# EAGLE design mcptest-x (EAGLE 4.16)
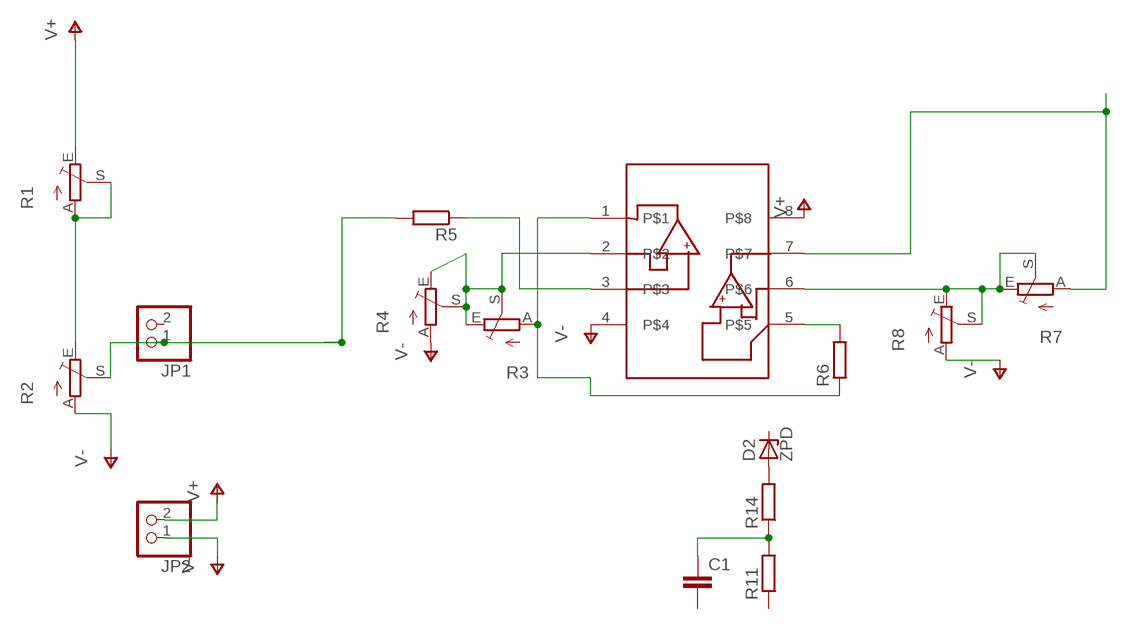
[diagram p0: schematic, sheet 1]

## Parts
C1  C-EU025_050-035X075  [C025_050-035X075]
D2  ZPD  [DO35Z10]
JP1  PINHD-1X2  [1X02]
JP2  PINHD-1X2  [1X02]
R1  TRIM_EU-LI15  [LI15]
R2  TRIM_EU-LI15  [LI15]
R3  TRIM_EU-LI15  [LI15]
R4  TRIM_EU-LI15  [LI15]
R5  R-EU_0207/15  [0207/15]
R6  R-EU_0207/15  [0207/15]
R7  TRIM_EU-LI15  [LI15]
R8  TRIM_EU-LI15  [LI15]
R11  R-EU_0207/10  [0207/10]
R14  R-EU_0207/10  [0207/10]
U$1  MCP6042SOIC  [SO-08]

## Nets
N$1: R7.A U$1.7
N$2: R7.E R7.S R8.E R8.S U$1.6
N$3: R3.E R3.S R4.E R4.S U$1.2
N$4: R3.A R6.1 U$1.1
N$5: R6.2 U$1.5
N$6: R1.A R1.S R2.E
N$7: R5.1 U$1.3
N$8: JP1.1 R2.S R5.2
N$9: C1.1 R11.2 R14.1
N$11: D2.A R14.2
V+: JP2.2 R1.E U$1.8
V-: JP2.1 R2.A R4.A R8.A U$1.4
Unconnected: C1.2 D2.C JP1.2 R11.1

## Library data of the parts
C1 = rcl:C-EU: CAPACITOR, European symbol
D2 = diode:ZPD: Z DIODE
JP1 JP2 = pinhead:PINHD-1X2: PIN HEADER
R1-R4 R7 R8 = pot:TRIM_EU-: POTENTIOMETER
R5 R6 = rcl:R-EU_: RESISTOR, European symbol
R11 R14 = rcl-2:R-EU_: RESISTOR, European symbol
U$1 = microchip-3:MCP6042

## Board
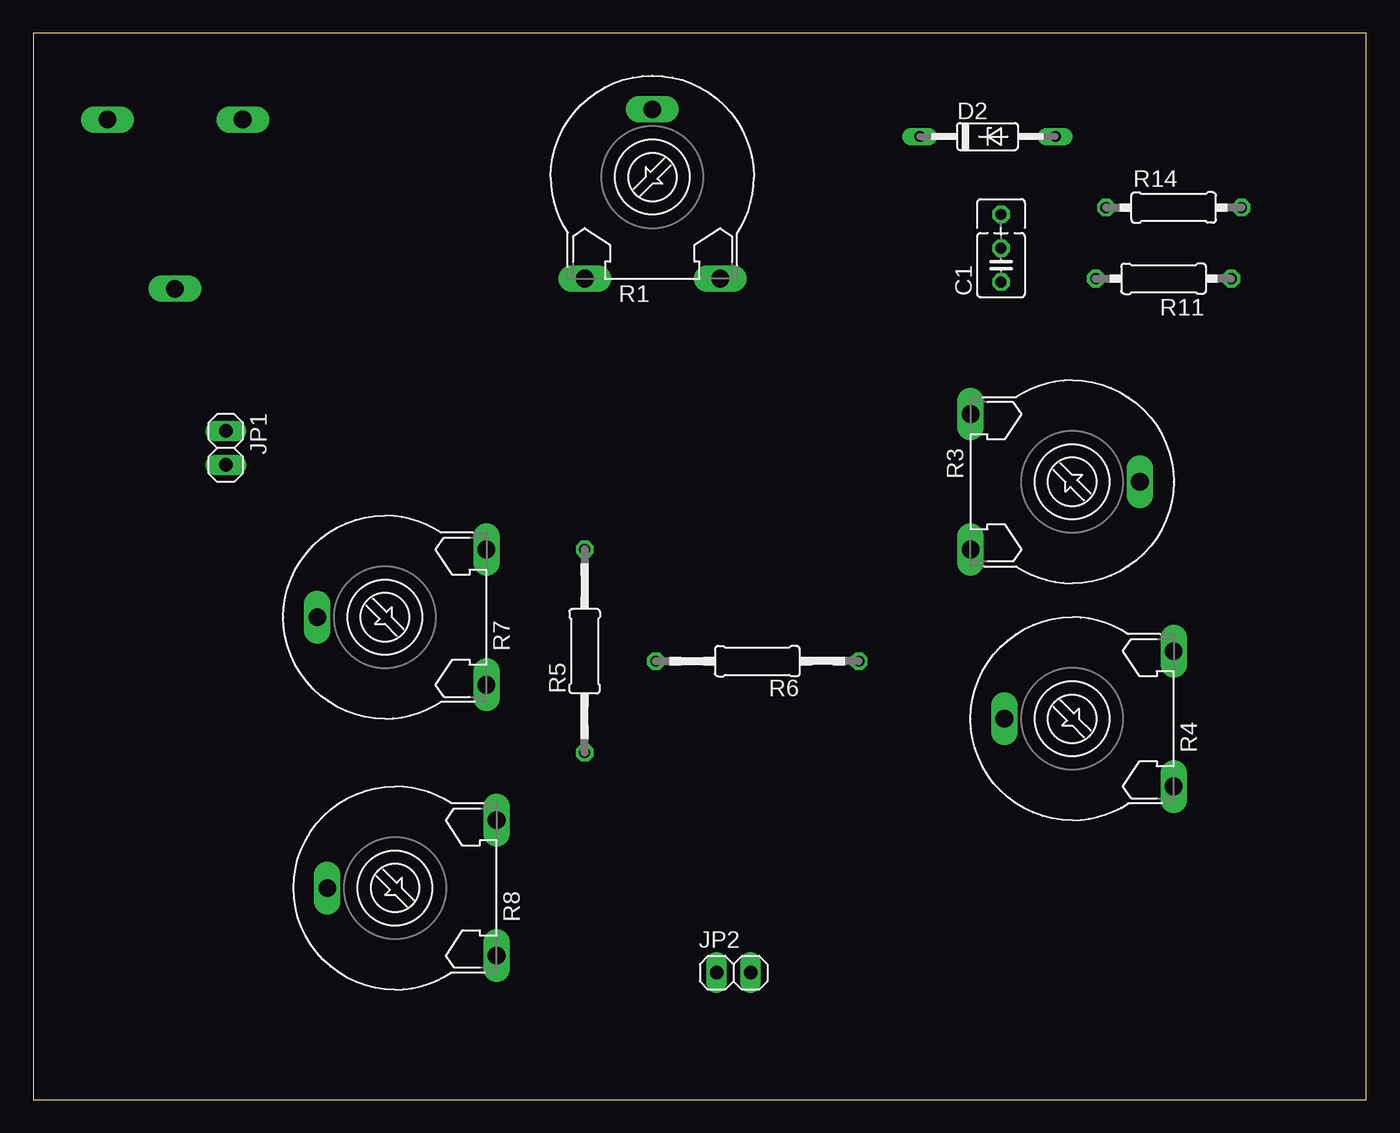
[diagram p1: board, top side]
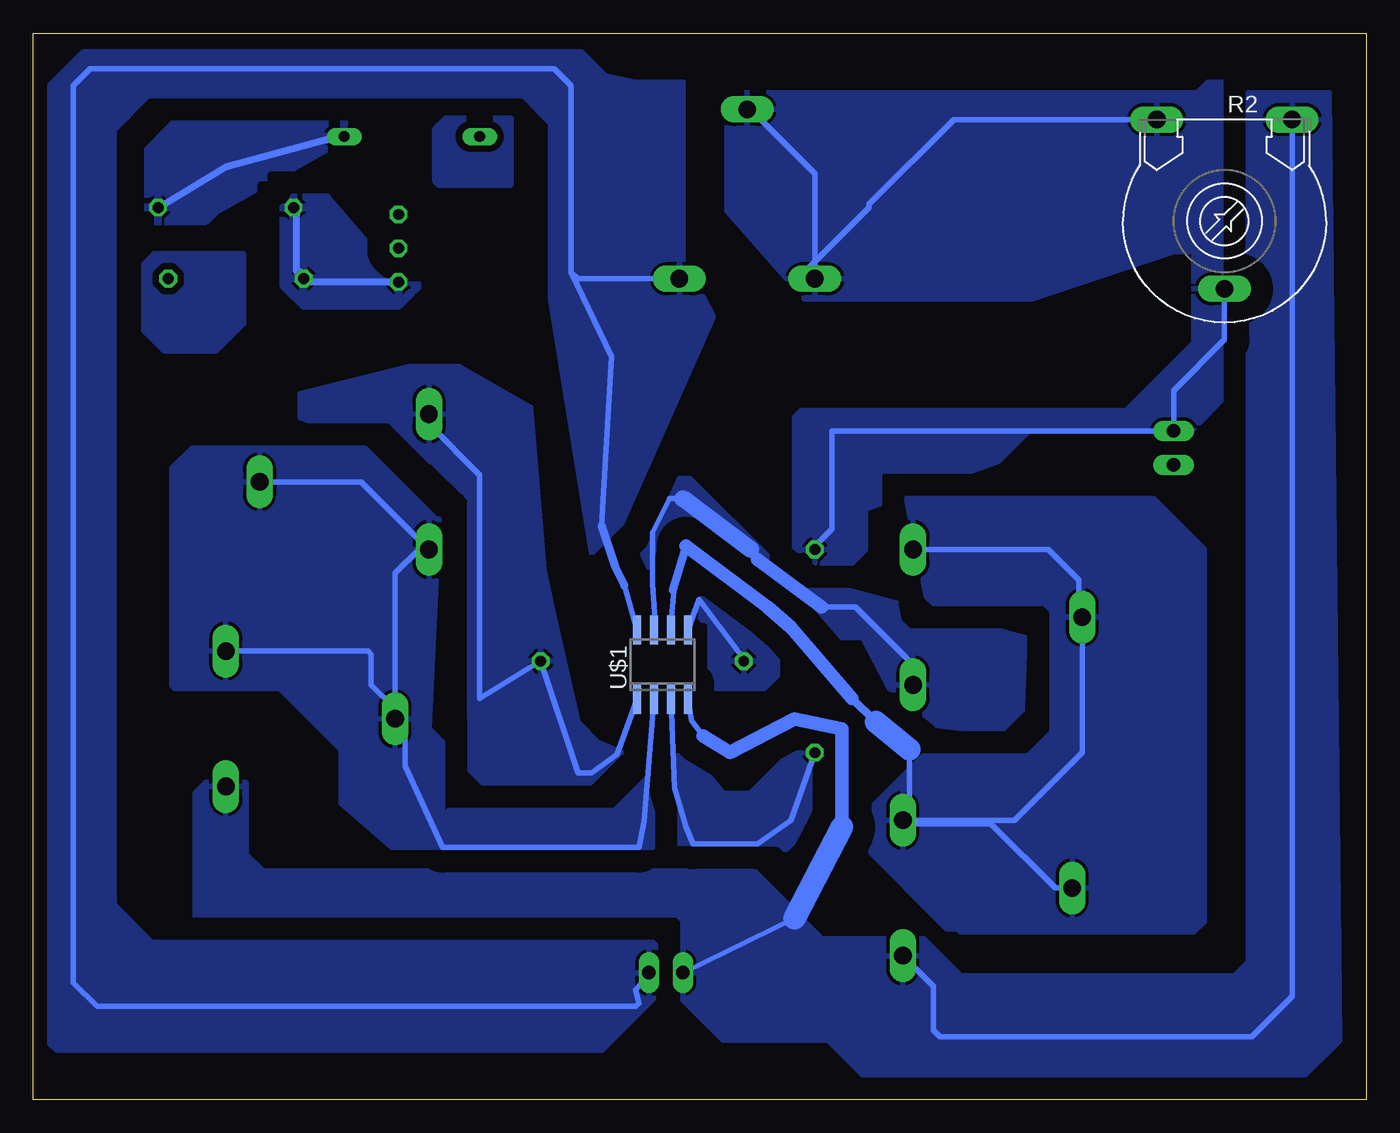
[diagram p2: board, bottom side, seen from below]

Size 100 x 80 mm. Coordinates in mm from the lower left corner, seen from the top.
Outline: 0,0 100,0 100,80 0,80 0,0
Copper layers (1*16): Top 0.035mm / dielectric 1.5mm / Bottom 0.035mm
Design rules "default": minimum track width 20mil, minimum drill 24mil, track to track 20mil, track to pad 20mil, pad to pad 8mil, via to via 8mil, smd to smd 8mil, copper to edge 40mil, drill to drill 8mil, minimum pad ring 10mil, minimum via ring 8mil, stop-mask expansion 4mil, vias tented up to drill 0mil, thermal gap 10mil

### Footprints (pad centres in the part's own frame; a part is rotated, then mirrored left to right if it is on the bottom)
C025_050-035X075 = drill 0.813 octagon: 1 -1.27,0; 2 1.27,0; 3 3.81,0
DO35Z10 = drill 0.813 long: A 5.08,0; C -5.08,0
1X02 = drill 1.016 long: 1 -1.27,0; 2 1.27,0
LI15 = drill 1.321 long: A -5.08,-7.62; E 5.08,-7.62; S 0,5.08
0207/15 = drill 0.813 octagon: 1 -7.62,0; 2 7.62,0
0207/10 = drill 0.813 octagon: 1 -5.08,0; 2 5.08,0
SO-08 = smd 0.6 x 2.2: 1 -1.905,-2.6; 2 -0.635,-2.6; 3 0.635,-2.6; 4 1.905,-2.6; 5 1.905,2.6; 6 0.635,2.6; 7 -0.635,2.6; 8 -1.905,2.6

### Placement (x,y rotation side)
C1  72.61,62.61 90 top
D2  71.59,72.26 0 top
JP1  14.44,48.89 270 top
JP2  52.54,9.52 0 top
R1  46.44,69.21 0 top
R2  10.63,65.91 180 bottom
R3  77.94,46.35 270 top
R4  77.94,28.57 90 top
R5  41.36,33.65 90 top
R6  54.32,32.89 180 top
R7  26.38,36.19 90 top
R8  27.14,15.87 90 top
R11  84.8,61.59 180 top
R14  85.56,66.92 0 top
U$1  52.79,32.63 0 bottom

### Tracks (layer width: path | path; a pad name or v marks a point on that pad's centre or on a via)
N$1
  Bottom 0.406: R7.A 34,32.63 38.32,36.95 40.86,36.95 | 45.68,40.51 46.19,41.27 | 51.27,45.08 52.29,45.08 53.56,42.54 53.56,38.73 53.3,35.43 53.43,35.3 U$1.7
  Bottom 1.016: 40.86,36.95 45.68,40.51
  Bottom 1.27: 46.19,41.27 51.27,45.08
  pour Bottom (isolate 1.676, rank 4): 53.56,36.7 53.56,38.73 54.83,40.76 54.83,44.32 52.29,46.6 50.76,46.6 44.41,40.25 40.35,40.25 39.84,38.48 25.62,34.67 25.87,27.3 34.51,28.32 37.81,34.67 40.09,34.67 44.41,38.98 46.95,38.98 51.52,43.56
N$2
  Bottom 0.406: R8.S 23.33,15.87 28.16,20.7 35.01,20.7 R8.E | R8.E 26.38,20.95 21.3,26.03 21.3,35.94 | 21.55,36.44 R7.S 21.3,35.94 | 52.03,38.22 51.91,38.6 52.16,35.81 52.03,35.94 52.03,35.17 52.09,35.23 U$1.6 | 34.25,26.28 34.25,21.71 34.51,21.46 34.51,21.2 R8.E | R7.E 23.84,41.27 21.55,38.98 21.55,36.19 21.3,35.94
  Bottom 0.61: 51.02,41.52 52.03,38.22 | 36.79,28.32 38.57,30.09
  Bottom 1.016: 51.02,41.52 44.92,36.95 43.14,35.43 38.57,30.09
  Bottom 1.676: 34.25,26.28 36.79,28.32
  pour Bottom (isolate 1.676, rank 2): 34.51,45.08 15.96,45.08 12.15,41.27 12.15,13.33 12.92,12.57 30.44,12.57 30.7,12.82 31.46,12.82 37.81,19.17 37.81,21.2 33.24,25.78 25.36,25.78 23.58,27.55 23.58,36.7 24.09,37.21 32.47,37.21 32.98,37.71
N$3
  Bottom 0.406: U$1.2 54.19,20.82 54.57,18.92 69.3,18.92 72.1,25.01 72.1,28.06 72.86,28.82 R4.S 72.86,29.33 | 72.86,29.33 72.86,39.49 70.95,41.4 70.7,41.65 | 70.7,41.65 70.57,41.78 70.83,41.78 | R4.E 74.89,33.65 74.64,33.4 74.64,31.11 72.86,29.33 | 70.7,41.65 70.57,41.52 | R3.S 75.4,46.35 70.7,41.65
  Bottom 0.508: R3.E 70.83,41.27 70.95,41.4
  pour Bottom (isolate 1.676, rank 2): 69.56,43.56 69.81,43.56 75.15,48.89 88.1,48.89 89.62,47.37 89.62,31.11 89.37,30.86 81.5,30.86 76.92,26.28 76.92,22.22 73.11,18.92 53.56,18.92 53.56,24.25 53.81,24.25 56.35,21.71 68.8,21.71 69.3,21.2 69.3,26.79 70.32,27.81
N$4
  Bottom 0.406: U$1.1 56.22,25.9 58.13,24.51 59.14,24.51 R6.1 66.51,30.09 66.51,46.86 70.32,50.67 R3.A
  pour Bottom (isolate 1.676, rank 3): 55.84,26.03 55.84,24.25 56.6,23.49 66,23.49 67.27,24.76 67.27,45.08 70.07,47.87 70.57,47.87 79.97,51.18 79.97,52.95 71.84,54.99 68.03,54.99 62.7,51.94 61.68,39.75 60.92,36.19 59.14,28.32 57.62,26.79
N$5
  Bottom 0.406: U$1.5 50.06,37.52 46.95,33.4 R6.2 46.7,32.38
  pour Bottom (isolate 1.676, rank 3): 44.16,34.67 44.16,31.87 45.17,30.86 48.98,30.86 49.24,31.11 49.24,35.68 49.49,35.94 49.75,35.94 50.51,36.7 50.51,37.97 49.75,38.73
N$6
  Bottom 0.406: R2.E 30.95,73.53 37.3,67.18 37.3,66.92 42.13,62.1 | R1.S 46.19,74.29 41.36,69.46 R1.A
  pour Bottom (isolate 1.676, rank 3): 11.39,75.56 47.97,75.56 47.97,66.67 42.13,60.07 25.11,60.07 14.44,63.62 11.39,63.62
N$7
  Bottom 0.406: U$1.3 51.91,23.36 51.02,20.44 50.51,19.17 45.68,19.17 43.14,20.95 R5.1
  pour Bottom (isolate 1.676, rank 3): 40.6,27.05 40.6,22.98 40.86,22.73 40.86,21.46 43.9,18.41 51.78,18.41 51.78,20.19 52.54,20.95 52.54,29.33 51.78,27.3 48.22,22.98 46.19,22.98 42.89,26.28
N$8
  Bottom 0.406: R5.2 41.62,41.27 40.09,42.79 40.09,50.16 JP1.1 14.19,50.16 14.44,50.41 14.44,53.21 10.63,57.02 R2.S
  pour Bottom (isolate 1.676, rank 3): 37.55,44.32 37.55,41.27 38.57,40.25 42.38,40.25 42.89,40.76 42.89,51.18 42.38,51.68 18,51.68 12.92,56.76 12.92,75.31 11.9,76.32 8.34,76.32 7.84,75.81 7.84,68.7 10.38,66.16 10.38,52.95 13.17,50.16 25.36,50.16 27.65,47.87
N$9
  Bottom 0.508: C1.1 79.21,61.34 R11.2 79.97,62.1 80.23,62.1 80.23,66.42 R14.1
  pour Bottom (isolate 1.676, rank 3): 77.94,67.69 80.48,67.69 81.24,66.92 81.24,61.08 79.72,59.56 72.61,59.56 71.08,61.08 72.1,61.08 73.11,62.1
N$10
  pour Bottom (isolate 0.254, rank 4): 64.22,73.53 69.05,73.53 69.81,72.77 69.81,68.96 69.56,68.7 64.22,68.7
N$11
  Bottom 0.508: D2.A 77.94,72 85.56,69.97 90.13,67.18 R14.2
  pour Bottom (isolate 1.676, rank 4): 74.13,73.53 90.39,73.53 91.4,72.51 91.4,66.16 91.66,65.91 87.08,65.91 86.32,66.67
N$14
  pour Bottom (isolate 0.254, rank 3): 84.29,63.37 90.89,63.37 91.66,62.61 91.66,57.78 90.13,56.26 86.32,56.26 84.29,58.29
V+
  Bottom 0.406: R1.E 59.14,61.59 59.65,62.1 | 59.65,62.1 59.65,76.07 60.92,77.34 95.72,77.34 96.99,76.07 96.99,8.76 95.21,6.98 54.83,6.98 54.57,7.23 54.83,8.25 54.32,8.76 JP2.2 | 55.65,38.54 U$1.8 | 57.37,43.05 56.6,55.75 59.65,62.1
  Bottom 0.61: 55.65,38.54 56.35,40 57.37,43.05
  pour Bottom: 51.27,63.11 51.27,76.32 54.83,76.32 57.11,76.83 58.89,78.61 96.23,78.61 98.77,76.07 98.77,4.19 98.26,3.68 57.37,3.68 53.3,7.74 53.3,11.55 53.56,11.81 91.15,11.81 93.94,14.6 93.94,72.77 91.4,75.31 63.21,75.31 61.18,73.27 61.18,60.07 58.13,41.02 55.84,43.3 48.98,58.8
V-
  Bottom 0.406: 42.89,13.58 JP2.1 | 49.75,27.3 50.63,28.44 U$1.4 | R2.A 5.55,7.74 8.6,4.69 31.97,4.69 32.47,5.2 32.47,8.5 R8.A
  Bottom 1.016: 39.33,20.44 39.33,27.81 42.89,28.57 47.71,26.03 49.75,27.3
  Bottom 1.676: 42.89,13.58 39.33,20.44
  pour Bottom (isolate 1.676, rank 2): 2.76,75.56 8.85,75.56 8.85,10.28 9.87,9.27 30.44,9.27 33.24,12.06 40.86,12.06 45.94,17.14 82.77,17.14 84.04,18.41 84.04,23.74 84.29,24 86.83,24 87.85,22.98 87.85,13.58 86.58,12.31 56.1,12.31 48.22,4.44 40.35,4.44 37.3,1.39 5.04,1.39 1.99,4.44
